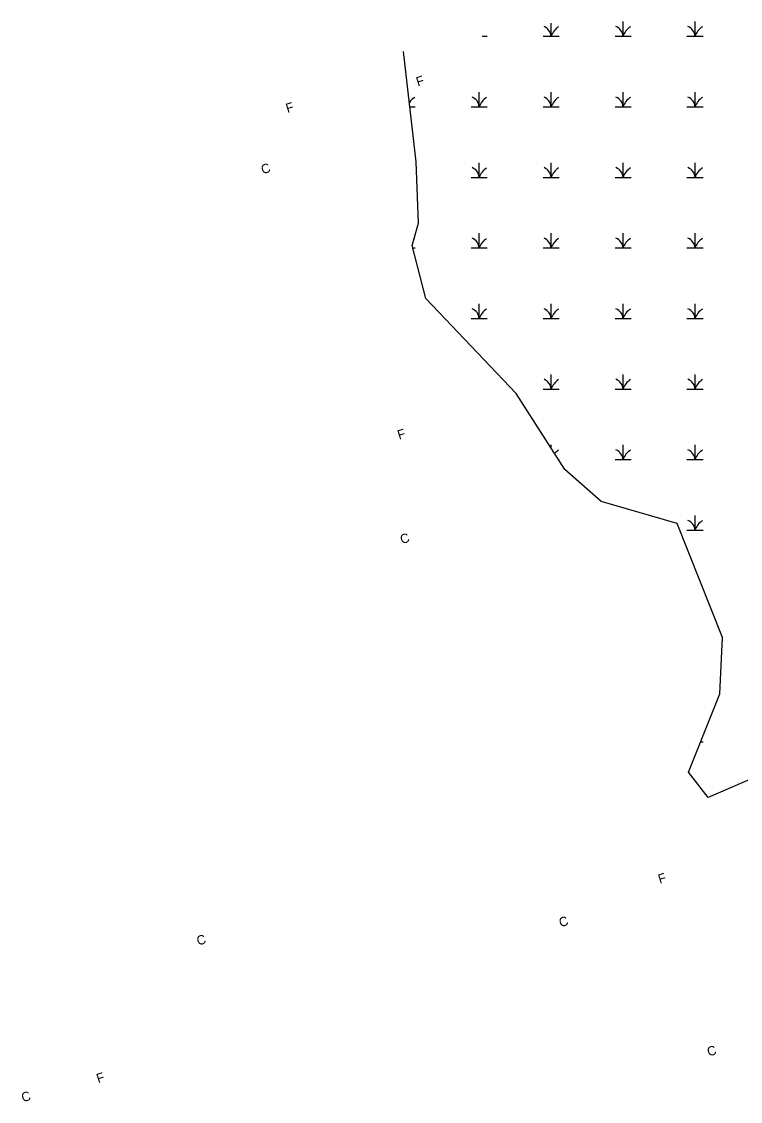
# Model space of a CAD drawing. Extents: x 2166958 to 2178986, y 64620 to 71122.
# Drawn here: x 2167710 to 2168096, y 65481 to 66061 of the extents above; entities that cross this region are included whole.
import ezdxf

# ---------------------------------------------------------------- set-up
doc = ezdxf.new("R2010")
doc.units = 0
for name, color, linetype in [('Default', 7, 'Continuous'), ('Prop Horizontal Alignment', 7, 'Continuous'), ('Prop Horizontal Alignment Station Label', 7, 'Continuous')]:
    doc.layers.add(name, color=color, linetype=linetype)

msp = doc.modelspace()

# ---------------------------------------------------------------- linework, layer by layer
at = {"layer": 'Prop Horizontal Alignment'}
msp.add_lwpolyline([(2168476.74, 65816.71), (2168078.65, 65644.28), (2168068.11, 65657.94), (2168084.89, 65699.98), (2168086.36, 65730.25), (2168062.03, 65791.53), (2168021.16, 65803.33), (2168001.62, 65820.59), (2167975.63, 65861.24), (2167927.1, 65912.33), (2167919.81, 65940.77), (2167923.18, 65952.74), (2167921.92, 65985.66), (2167915.23, 66044.99)], dxfattribs=at)
at = {"layer": 'Prop Horizontal Alignment Station Label'}
for p, q in [((2167994.34, 66053.14), (2167994.34, 66060.28)), ((2168032.94, 66053.14), (2168032.94, 66061.03)), ((2168071.54, 66053.14), (2168071.54, 66061.03)), ((2167957.4, 66053.14), (2167960.04, 66053.14)), ((2167990.04, 66053.14), (2167998.64, 66053.14)), ((2168028.64, 66053.14), (2168037.24, 66053.14)), ((2168067.24, 66053.14), (2168075.84, 66053.14)), ((2167955.73, 66015.25), (2167955.73, 66023.14)), ((2167994.34, 66015.25), (2167994.34, 66023.14)), ((2168032.94, 66015.25), (2168032.94, 66023.14)), ((2168071.54, 66015.25), (2168071.54, 66023.14)), ((2167918.58, 66015.25), (2167921.43, 66015.25)), ((2167951.43, 66015.25), (2167960.04, 66015.25)), ((2167990.04, 66015.25), (2167998.64, 66015.25)), ((2168028.64, 66015.25), (2168037.24, 66015.25)), ((2168067.24, 66015.25), (2168075.84, 66015.25)), ((2167955.73, 65977.36), (2167955.73, 65985.25)), ((2167994.34, 65977.36), (2167994.34, 65985.25)), ((2168032.94, 65977.36), (2168032.94, 65985.25)), ((2168071.54, 65977.36), (2168071.54, 65985.25)), ((2167951.43, 65977.36), (2167960.04, 65977.36)), ((2167990.04, 65977.36), (2167998.64, 65977.36)), ((2168028.64, 65977.36), (2168037.24, 65977.36)), ((2168067.24, 65977.36), (2168075.84, 65977.36)), ((2167955.73, 65939.47), (2167955.73, 65947.36)), ((2167994.34, 65939.47), (2167994.34, 65947.36)), ((2168032.94, 65939.47), (2168032.94, 65947.36)), ((2168071.54, 65939.47), (2168071.54, 65947.36)), ((2167920.14, 65939.47), (2167921.43, 65939.47)), ((2167951.43, 65939.47), (2167960.04, 65939.47)), ((2167990.04, 65939.47), (2167998.64, 65939.47)), ((2168028.64, 65939.47), (2168037.24, 65939.47)), ((2168067.24, 65939.47), (2168075.84, 65939.47)), ((2167955.73, 65901.58), (2167955.73, 65909.47)), ((2167994.34, 65901.58), (2167994.34, 65909.47)), ((2168032.94, 65901.58), (2168032.94, 65909.47)), ((2168071.54, 65901.58), (2168071.54, 65909.47)), ((2167951.43, 65901.58), (2167960.04, 65901.58)), ((2167990.04, 65901.58), (2167998.64, 65901.58)), ((2168028.64, 65901.58), (2168037.24, 65901.58)), ((2168067.24, 65901.58), (2168075.84, 65901.58)), ((2167994.34, 65863.69), (2167994.34, 65871.58)), ((2168032.94, 65863.69), (2168032.94, 65871.58)), ((2168071.54, 65863.69), (2168071.54, 65871.58)), ((2167990.04, 65863.69), (2167998.64, 65863.69)), ((2168028.64, 65863.69), (2168037.24, 65863.69)), ((2168067.24, 65863.69), (2168075.84, 65863.69)), ((2167994.34, 65831.98), (2167994.34, 65833.69)), ((2168032.94, 65825.8), (2168032.94, 65833.69)), ((2168071.54, 65825.8), (2168071.54, 65833.69)), ((2167998.29, 65825.8), (2167998.64, 65825.8)), ((2168028.64, 65825.8), (2168037.24, 65825.8)), ((2168067.24, 65825.8), (2168075.84, 65825.8)), ((2168071.54, 65787.91), (2168071.54, 65795.8)), ((2168067.24, 65787.91), (2168075.84, 65787.91)), ((2168074.62, 65674.24), (2168075.84, 65674.24))]:
    msp.add_line(p, q, dxfattribs=at)
for centre, radius, start, end in [((2167988.2, 66052.7), 6.15, 4.14034, 67.53497), ((2168003.46, 66050.11), 9.61, 122.12745, 161.62219), ((2168026.8, 66052.7), 6.15, 4.14034, 67.53497), ((2168042.06, 66050.11), 9.61, 122.12745, 161.62219), ((2168065.41, 66052.7), 6.15, 4.14034, 67.53497), ((2168080.66, 66050.11), 9.61, 122.12745, 161.62219), ((2167926.25, 66012.22), 9.61, 122.12745, 145.70088), ((2167949.6, 66014.81), 6.15, 4.14034, 67.53497), ((2167964.86, 66012.22), 9.61, 122.12745, 161.62219), ((2167988.2, 66014.81), 6.15, 4.14034, 67.53497), ((2168003.46, 66012.22), 9.61, 122.12745, 161.62219), ((2168026.8, 66014.81), 6.15, 4.14034, 67.53497), ((2168042.06, 66012.22), 9.61, 122.12745, 161.62219), ((2168065.41, 66014.81), 6.15, 4.14034, 67.53497), ((2168080.66, 66012.22), 9.61, 122.12745, 161.62219), ((2167949.6, 65976.92), 6.15, 4.14034, 67.53497), ((2167964.86, 65974.33), 9.61, 122.12745, 161.62219), ((2167988.2, 65976.92), 6.15, 4.14034, 67.53497), ((2168003.46, 65974.33), 9.61, 122.12745, 161.62219), ((2168026.8, 65976.92), 6.15, 4.14034, 67.53497), ((2168042.06, 65974.33), 9.61, 122.12745, 161.62219), ((2168065.41, 65976.92), 6.15, 4.14034, 67.53497), ((2168080.66, 65974.33), 9.61, 122.12745, 161.62219), ((2167926.25, 65936.44), 9.61, 122.12745, 124.41127), ((2167949.6, 65939.03), 6.15, 4.14034, 67.53497), ((2167964.86, 65936.44), 9.61, 122.12745, 161.62219), ((2167988.2, 65939.03), 6.15, 4.14034, 67.53497), ((2168003.46, 65936.44), 9.61, 122.12745, 161.62219), ((2168026.8, 65939.03), 6.15, 4.14034, 67.53497), ((2168042.06, 65936.44), 9.61, 122.12745, 161.62219), ((2168065.41, 65939.03), 6.15, 4.14034, 67.53497), ((2168080.66, 65936.44), 9.61, 122.12745, 161.62219), ((2167949.6, 65901.14), 6.15, 4.14034, 67.53497), ((2167964.86, 65898.55), 9.61, 122.12745, 161.62219), ((2167988.2, 65901.14), 6.15, 4.14034, 67.53497), ((2168003.46, 65898.55), 9.61, 122.12745, 161.62219), ((2168026.8, 65901.14), 6.15, 4.14034, 67.53497), ((2168042.06, 65898.55), 9.61, 122.12745, 161.62219), ((2168065.41, 65901.14), 6.15, 4.14034, 67.53497), ((2168080.66, 65898.55), 9.61, 122.12745, 161.62219), ((2167988.2, 65863.25), 6.15, 4.14034, 67.53497), ((2168003.46, 65860.66), 9.61, 122.12745, 161.62219), ((2168026.8, 65863.25), 6.15, 4.14034, 67.53497), ((2168042.06, 65860.66), 9.61, 122.12745, 161.62219), ((2168065.41, 65863.25), 6.15, 4.14034, 67.53497), ((2168080.66, 65860.66), 9.61, 122.12745, 161.62219), ((2168003.46, 65822.77), 9.61, 122.12745, 139.05833), ((2168026.8, 65825.36), 6.15, 4.14034, 67.53497), ((2168042.06, 65822.77), 9.61, 122.12745, 161.62219), ((2168065.41, 65825.36), 6.15, 4.14034, 67.53497), ((2168080.66, 65822.77), 9.61, 122.12745, 161.62219), ((2168065.41, 65787.47), 6.15, 4.14034, 67.53497), ((2168080.66, 65784.88), 9.61, 122.12745, 161.62219)]:
    msp.add_arc(centre, radius, start, end, dxfattribs=at)

# ---------------------------------------------------------------- texts
at = {"layer": 'Default'}
for s, p in [('F', (2167922.81, 66026.18)), ('F', (2167852.89, 66011.91)), ('C', (2167839.61, 65979.02)), ('F', (2167912.79, 65836.51)), ('C', (2167914.24, 65780.39)), ('F', (2168052.64, 65598.01)), ('C', (2167999.43, 65574.64)), ('C', (2167805.04, 65564.8)), ('C', (2168078.92, 65505.22)), ('F', (2167751.31, 65490.91)), ('C', (2167711.03, 65480.67))]:
    msp.add_text(s, height=5, rotation=17.18233, dxfattribs=at).set_placement(p)

doc.saveas('drawing.dxf')
